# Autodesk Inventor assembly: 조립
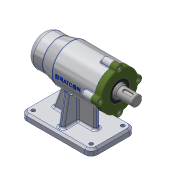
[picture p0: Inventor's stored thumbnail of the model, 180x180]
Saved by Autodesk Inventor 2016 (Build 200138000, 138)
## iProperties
Created: 2019-07
Part Number: 조립
Material: 일반
Document SubType Name: Assembly
Designer: 605-11
Author: 605-11
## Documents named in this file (9)
- C:\Users\605-11\Desktop\490704V1065\조립.iam
- C:\Users\605-11\Desktop\490704V1065\1.본체.ipt
- C:\Users\605-11\Desktop\490704V1065\베어링 6004.ipt
- C:\Users\605-11\Desktop\490704V1065\축.ipt
- C:\Users\605-11\Desktop\490704V1065\베어링 51202.ipt
- C:\Users\605-11\Desktop\490704V1065\어댑터슬리브.ipt
- C:\Users\605-11\Desktop\490704V1065\볼트 M4.ipt
- C:\Users\605-11\Desktop\490704V1065\커버.ipt
- C:\Users\605-11\Desktop\490704V1065\오일 실.ipt
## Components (1 placed, 1 different names)
1. 1.본체:1
